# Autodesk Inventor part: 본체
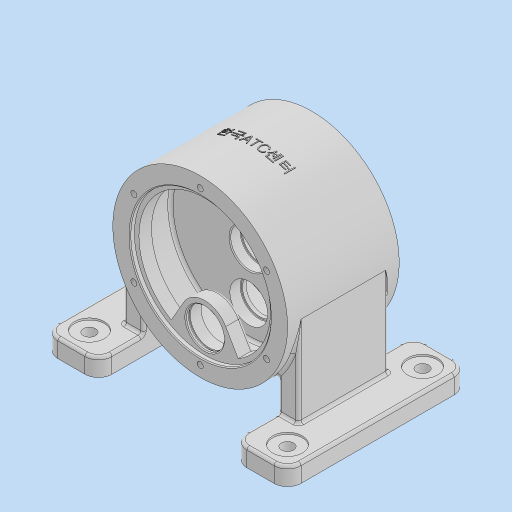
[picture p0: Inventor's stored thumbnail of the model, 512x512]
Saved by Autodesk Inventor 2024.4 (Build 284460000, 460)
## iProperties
Created: 2025-12
Part Number: 본체
Material: 일반
Document SubType Name: Modeling
Designer: home
Density: 8.94 g/cm^3
Appearance: 기본값
Mass: 18629.8 g
Surface Area: 3057.76 cm^2
Volume: 2083.88 cm^3
Author: home
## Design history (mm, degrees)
sketch "스케치1"
  geometry: L1 (-135, 100)-(135, 100); L2 (135, 100)-(135, -100); L3 (135, -100)-(-135, -100); L4 (-135, -100)-(-135, 100); L5 (-135, 100)-(135, -100); L6 (135, 100)-(-135, -100); 1 further point
  constraints: 12 end point, 2 midpoint, 2 parallel, 1 horizontal, 1 perpendicular
  dimensions: "d0" = 270 distance of L2.end L3.end; "d1" = 200 distance of L1.end L2.end
extrude "돌출1" new body sketch "스케치1" distance "d2" = 20; taper "d3" = 0 deg
sketch "스케치2"
  geometry: L1 (135, 100)-(-135, 100) reference; L2 (-75, -100)-(75, -100); L3 (75, -100)-(75, 100); L4 (75, 100)-(-75, 100); L5 (-75, 100)-(-75, -100); L6 (-75, -100)-(75, 100); L7 (75, -100)-(-75, 100); 2 further points
  constraints: 12 end point, 2 midpoint, 2 parallel, 1 horizontal, 1 perpendicular, 1 point on line
  dimensions: "d4" = 150 distance of L2.start L2.end
extrude "돌출2" cut sketch "스케치2" extent not by distance; stored distance "d5" = 0; taper "d6" = 0 deg
fillet "모깎기1" dims "d7" = 15
sketch "스케치3"
  geometry: 5 further points
  constraints: 2 horizontal alignment, 2 vertical alignment
  dimensions: "d8" = 220 distance of point (110, -75) point (-110, -75); "d9" = 110 horizontal distance of point (0, 0) point (-110, -75); "d10" = 150 distance of point (110, -75) point (110, 75); "d11" = 75 vertical distance of point (0, 0) point (110, 75)
hole "구멍1" sketch "스케치3" at (-110, -75), (110, -75), (110, 75), (-110, 75) diameter "d12" = 13.5; stored, may be unused: countersink angle "d16" = 90 deg, drill point angle "d18" = 118 deg; dims "d13" = 6, "d14" = 33, "d15" = 2, "d17" = 8
sketch "스케치4"
  geometry: C1 r 97 at (0, 120); 1 further point
  constraints: 1 centre point, 1 vertical alignment
  dimensions: "d19" = 194 diameter of C1; "d20" = 120 distance of point (0, 0) C1.centre
extrude "돌출3" join sketch "스케치4" stored distance "d21" = 124; taper "d22" = 0 deg
sketch "스케치5"
  geometry: L1 (-75, 50)-(-97, 50); L2 (-97, 50)-(-97, -50); L3 (-97, -50)-(-75, -50); L4 (-75, -50)-(-75, 50); L5 (-75, 85)-(-75, -85) reference; L6 (75, -85)-(75, 85) reference; L7 (75, 50)-(97, 50); L8 (97, 50)-(97, -50); L9 (97, -50)-(75, -50); L10 (75, -50)-(75, 50); 5 further points
  constraints: 16 end point, 4 parallel, 2 equal length, 2 horizontal, 2 horizontal alignment, 2 midpoint, 2 perpendicular, 2 vertical alignment
  dimensions: "d23" = 100 distance of L1.end L2.end; "d24" = 22 distance of L1.start L1.end
extrude "돌출4" join sketch "스케치5" stored distance "d25" = 124; taper "d26" = 0 deg
fillet "모깎기2" dims "d27" = 3
sketch "스케치6"
  geometry: L1 (-75, 58.486)-(-75, 20) reference; L2 (75, 20)-(75, 58.486) reference; L3 (-75, 20)-(-75, 0) reference; L4 (-75, 8)-(-36.6, 30.17); L5 (0, 0)-(0, 19.085); L6 (75, 8)-(36.6, 30.17); L7 (75, 0)-(75, 20) reference; L8 (90, 0)-(75, 0) reference; A1 r 97 centre (0, 120) between (-75, 58.486) and (75, 58.486) reference; 1 further point
  constraints: 6 end point, 2 symmetric about line, 1 point on circle, 1 point on line, 1 vertical
  dimensions: "d28" = 60 deg angle of L1 L4; "d97" = 8 distance from line of L6.start L8
extrude "돌출5" join sketch "스케치6" stored distance "d30" = 12; taper "d31" = 0 deg
fillet "모깎기3" dims "d32" = 3
fillet "모깎기5" dims "d34" = 3
fillet "모깎기6" dims "d35" = 3
fillet "모깎기7" dims "d36" = 3
sketch "스케치7"
  geometry: C1 r 97 at (0, 0) reference; C2 r 78 at (0, 0); 1 further point
  constraints: 1 centre point, 1 coincident
  dimensions: "d37" = 156 diameter of C2
extrude "돌출6" cut sketch "스케치7" distance "d38" = 5; taper "d39" = 0 deg
sketch "스케치8"
  geometry: L1 (-23.383, -39)-(-37.148, -62.842); L2 (23.383, -39)-(37.148, -62.842); L3 (0, -52.5)-(0, 51.479); C1 r 78 at (0, 0) reference; A1 r 73 centre (0, 0) between (-37.148, -62.842) and (37.148, -62.842); A2 r 27 centre (0, -52.5) between (-23.383, -39) and (23.383, -39); 1 further point
  constraints: 6 end point, 4 point on circle, 2 centre point, 2 tangent, 1 coincident, 1 vertical, 1 vertical alignment
  dimensions: "d40" = 146 diameter of A1; "d41" = 52.5 distance of L3.start C1.centre; "d42" = 54 diameter of A2; "d43" = 30 deg angle of L3 L1; "d44" = 30 deg angle of L3 L2
extrude "돌출7" cut sketch "스케치8" distance "d45" = 17; taper "d46" = 0 deg
chamfer "모따기1" distance "d47" = 1; stored, may be unused: second distance "d48" = 2, angle "d49" = 45 deg
sketch "스케치9"
  geometry: L1 (-23.383, -39)-(-37.148, -62.842) reference; L2 (37.148, -62.842)-(23.383, -39) reference; C1 r 87 at (0, 0); A1 r 73 centre (0, 0) between (37.148, -62.842) and (-37.148, -62.842) reference; A2 r 27 centre (0, -52.5) between (23.383, -39) and (-23.383, -39) reference; 1 further point
  constraints: 1 centre point, 1 coincident
  dimensions: "d50" = 174 diameter of C1
extrude "돌출8" cut sketch "스케치9" distance "d51" = 32; taper "d52" = 0 deg
sketch "스케치10"
  geometry: C1 r 21 at (0, -52.5); A1 r 27 centre (0, -52.5) between (23.383, -39) and (-23.383, -39) reference; 1 further point
  constraints: 1 centre point, 1 coincident
  dimensions: "d53" = 42 diameter of C1
extrude "돌출9" cut sketch "스케치10" distance "d54" = 20; taper "d55" = 0 deg
sketch "스케치11"
  geometry: L1 (-57, 46.5)-(-57, 88.5) reference; L2 (-57, 67.5)-(-26.523, 67.5); L3 (-57, 88.5)-(-40, 88.5) reference; L4 (-53.95, 88.5)-(-52, 88.5); L5 (-52, 88.5)-(-52, 89.75); L6 (-52, 89.75)-(-53.95, 89.75); L7 (-53.95, 89.75)-(-53.95, 88.5); L8 (-40, 88.5)-(-40, 46.5) reference; 2 further points
  constraints: 10 end point, 2 horizontal, 2 parallel, 1 midpoint, 1 perpendicular, 1 point on line
  dimensions: "d56" = 44.5 diameter of L6 L2; "d57" = 1.95 distance of L5.end L6.end; "d58" = 12 distance between parallel lines of L5 L8
revolve "회전1" sketch "스케치11" stored, may be unused: angle "d59" = 90 deg
sketch "스케치12"
  geometry: C1 r 21 at (0, -52.5) reference; C2 r 87 at (0, 0) reference; C3 r 21 at (0, 0); 1 further point
  constraints: 1 centre point, 1 coincident
  dimensions: "d60" = 42 diameter of C3
extrude "돌출10" cut sketch "스케치12" distance "d61" = 12; taper "d62" = 0 deg
sketch "스케치13"
  geometry: C1 r 97 at (0, 0) reference; C2 r 78 at (0, 0); 1 further point
  constraints: 1 centre point, 1 coincident
  dimensions: "d63" = 156 diameter of C2
extrude "돌출11" cut sketch "스케치13" distance "d64" = 5; taper "d65" = 0 deg
chamfer "모따기2" distance "d66" = 1; stored, may be unused: second distance "d67" = 2, angle "d68" = 45 deg
sketch "스케치14"
  geometry: C1 r 78 at (0, 0) reference; C2 r 73 at (0, 0); 1 further point
  constraints: 1 centre point, 1 coincident
  dimensions: "d69" = 146 diameter of C2
extrude "돌출12" cut sketch "스케치14" distance "d70" = 17; taper "d71" = 0 deg
sketch "스케치15"
  geometry: C1 r 73 at (0, 0) reference; C2 r 87 at (0, 0); 1 further point
  constraints: 1 centre point, 1 coincident
  dimensions: "d72" = 174 diameter of C2
extrude "돌출13" cut sketch "스케치15" distance "d73" = 32; taper "d74" = 0 deg
sketch "스케치16"
  geometry: C1 r 21 at (0, 0) reference; C2 r 21 at (0, -52.5) reference; C3 r 19 at (0, 0); C4 r 19 at (0, -52.5); 1 further point
  constraints: 2 centre point, 2 coincident
  dimensions: "d75" = 38 diameter of C3; "d76" = 38 diameter of C4
extrude "돌출14" cut sketch "스케치16" extent not by distance; stored distance "d77" = 0; taper "d78" = 0 deg
fillet "모깎기8" dims "d79" = 3
chamfer "모따기3" distance "d80" = 1; stored, may be unused: second distance "d81" = 2, angle "d82" = 45 deg
sketch "스케치17" dims "d83" = 170
  geometry: C1 r 97 at (0, 0) reference; 3 further points
  constraints: 2 vertical alignment, 1 coincident, 2 other
hole "구멍2" sketch "스케치17" at (0, 85) diameter "d84" = 6.647; stored, may be unused: countersink angle "d88" = 90 deg, drill point angle "d90" = 118 deg; dims "d85" = 16, "d86" = 33, "d87" = 2, "d89" = 18
fillet "모깎기9" dims "d94" = 3
node "작업 평면1"
sketch "스케치18"
  geometry: L1 (-59.684, 19.988)-(59.684, 19.988); L2 (59.684, 19.988)-(59.684, -19.988); L3 (59.684, -19.988)-(-59.684, -19.988); L4 (-59.684, -19.988)-(-59.684, 19.988); 4 further points
  constraints: 2 midpoint, 1 coincident, 1 horizontal alignment, 1 vertical alignment, 2 other
feature "엠보싱1" sketch "스케치18" dims "d7" = 15, "d95" = 0.5, "d96" = 0
fillet "모깎기10" dims "d98" = 0.6
node "솔리드1"
pattern_circular "원형 패턴1" dims angle "d92" = 360 deg
mirror "미러1"
node "투영된 루프1"
node "투영된 루프2"
node "투영된 루프3"
node "투영된 루프4"
node "투영된 루프5"
node "투영된 루프6"
feature "A9D066F2-1C7D-4E18-AEED-F7BC21143FA4" dims "d84" = 6.647, "d85" = 16, "d86" = 33, "d87" = 2, "d88" = 90 deg, "d89" = 18, "d90" = 118 deg
